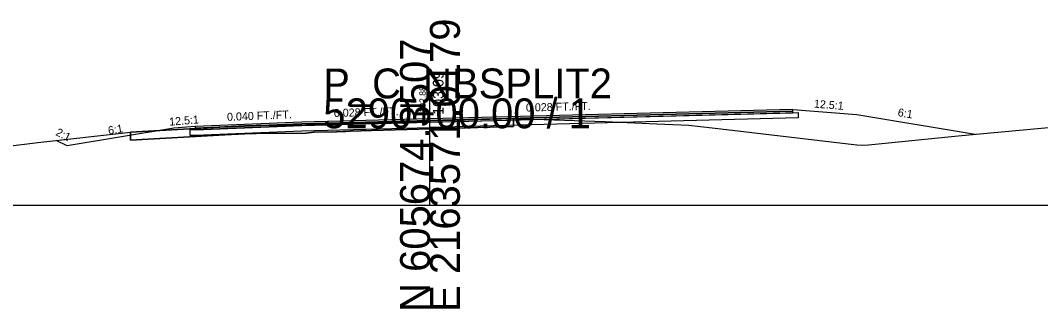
# Model space of a CAD drawing. Extents: x -26 to 1303, y -10 to 12038.
# Drawn here: x 111.6 to 207.2, y 5490.3 to 5517.3 of the extents above; entities that cross this region are included whole.
import ezdxf

# ---------------------------------------------------------------- set-up
doc = ezdxf.new("R2010")
doc.units = 0
for name, color, linetype in [('RD_GPK_XS_Cell', 7, 'Continuous'), ('RD_XS_Base', 7, 'Continuous'), ('RD_XS_ExGround', 7, 'Continuous'), ('RD_XS_ExPaveRet', 7, 'Continuous'), ('RD_XS_Greenside', 7, 'Continuous'), ('RD_XS_Pave', 7, 'Continuous'), ('RD_XS_PaveOvlay_CP', 7, 'Continuous'), ('RD_XS_TieSlope', 7, 'Continuous'), ('RD_XS_TX_Elev_EX', 7, 'Continuous'), ('RD_XS_TX_Elev_PR', 7, 'Continuous'), ('RD_XS_TX_ShdSlope', 7, 'Continuous'), ('RD_XS_TX_Slope', 7, 'Continuous')]:
    doc.layers.add(name, color=color, linetype=linetype)

msp = doc.modelspace()

# ---------------------------------------------------------------- linework, layer by layer
at = {"layer": 'RD_GPK_XS_Cell'}
for p, q in [((150, 5500), (150, 5510)), ((0, 5500), (150, 5500)), ((150, 5500), (300, 5500))]:
    msp.add_line(p, q, dxfattribs=at)
at = {"layer": 'RD_XS_Base'}
for p, q in [((150, 5507.772), (184.5, 5508.669)), ((174, 5508.396), (174, 5508.396)), ((174, 5508.396), (174, 5508.396)), ((184, 5508.656), (184, 5508.656)), ((184.5, 5508.669), (184.5, 5508.169)), ((184.5, 5508.636), (184.5, 5508.636)), ((138, 5507.46), (128, 5507.06)), ((150, 5507.772), (138, 5507.46)), ((138, 5507.46), (138, 5507.46)), ((184.5, 5508.169), (150, 5507.272)), ((150, 5507.272), (150, 5507.931)), ((150, 5507.931), (150, 5507.931)), ((150, 5507.931), (150, 5507.931)), ((150, 5507.931), (150, 5507.772)), ((150, 5507.772), (150, 5507.772)), ((150, 5507.272), (150, 5507.772)), ((150, 5507.772), (150, 5507.772)), ((150, 5507.772), (150, 5507.772)), ((174, 5507.896), (174, 5507.896)), ((174, 5507.896), (174, 5507.896)), ((128, 5507.06), (127.5, 5507.04)), ((127.5, 5507.04), (127.5, 5507.04)), ((127.5, 5507.04), (127.5, 5506.54)), ((127.5, 5506.54), (128, 5506.56)), ((128, 5507.06), (128, 5507.06)), ((128, 5506.56), (138, 5506.96)), ((128, 5506.56), (128, 5506.56)), ((138, 5506.96), (150, 5507.272)), ((138, 5506.96), (138, 5506.96)), ((150, 5507.272), (150, 5507.272))]:
    msp.add_line(p, q, dxfattribs=at)
at = {"layer": 'RD_XS_ExGround'}
msp.add_lwpolyline([(110.228, 5505.5), (113.26, 5505.871), (121.947, 5506.848), (130.783, 5507.333), (132.65, 5507.43), (133.697, 5507.462), (138.362, 5507.503), (139.162, 5507.596), (141.245, 5507.62), (141.848, 5507.644), (142.105, 5507.664), (142.506, 5507.669), (144.524, 5507.728), (157.841, 5508.109), (166.427, 5507.826), (171.259, 5507.611), (174.249, 5507.497), (176.44, 5507.25), (190.003, 5505.655), (190.532, 5505.607), (191.108, 5505.662), (199.491, 5506.499), (209.323, 5507.413)], dxfattribs=at)
at = {"layer": 'RD_XS_ExPaveRet'}
for points in [[(157.841, 5508.109), (157.841, 5508.109), (157.841, 5508.109), (157.841, 5507.359), (157.841, 5507.359), (144.524, 5506.978), (144.524, 5506.978), (142.506, 5506.919), (142.105, 5506.914), (142.105, 5506.914), (142.105, 5506.914), (141.848, 5506.894), (141.848, 5506.894), (141.245, 5506.87), (141.245, 5506.87), (141.245, 5506.87), (139.162, 5506.846), (138.362, 5506.753), (138.362, 5506.753), (133.697, 5506.712), (132.65, 5506.68), (132.65, 5506.68), (132.65, 5506.68), (130.783, 5506.583), (130.783, 5506.583), (121.948, 5506.098), (121.948, 5506.848), (121.948, 5506.848), (130.783, 5507.333), (130.783, 5507.333), (132.65, 5507.43), (132.65, 5507.43), (132.65, 5507.43), (133.697, 5507.462), (138.362, 5507.503), (138.362, 5507.503), (139.162, 5507.596), (141.245, 5507.62), (141.245, 5507.62), (141.245, 5507.62), (141.848, 5507.644), (141.848, 5507.644), (142.105, 5507.664), (142.105, 5507.664), (142.105, 5507.664), (142.506, 5507.669), (144.524, 5507.728), (144.524, 5507.728), (157.841, 5508.109)], [(144.524, 5507.728), (142.506, 5507.669), (142.105, 5507.664), (141.848, 5507.644), (141.245, 5507.62), (139.162, 5507.596), (138.362, 5507.503), (133.697, 5507.462), (132.65, 5507.43), (130.783, 5507.333), (121.948, 5506.848), (121.948, 5506.098), (130.783, 5506.583), (132.65, 5506.68), (133.697, 5506.712), (138.362, 5506.753), (139.162, 5506.846), (141.245, 5506.87), (141.848, 5506.894), (142.105, 5506.914), (142.506, 5506.919), (144.524, 5506.978), (157.841, 5507.359), (157.841, 5508.109), (144.524, 5507.728)]]:
    msp.add_lwpolyline(points, dxfattribs=at)
at = {"layer": 'RD_XS_Greenside'}
for p, q in [((190, 5508.494), (201.081, 5506.647)), ((126, 5507.218), (116, 5505.551)), ((116, 5505.551), (114.974, 5506.064))]:
    msp.add_line(p, q, dxfattribs=at)
at = {"layer": 'RD_XS_Pave'}
for p, q in [((184, 5508.974), (150, 5508.09)), ((184, 5508.815), (150, 5507.931)), ((150, 5507.931), (184, 5508.815)), ((150, 5507.772), (184, 5508.656)), ((174, 5508.714), (174, 5508.714)), ((174, 5508.714), (174, 5508.714)), ((174, 5508.555), (174, 5508.555)), ((174, 5508.555), (174, 5508.555)), ((174, 5508.555), (174, 5508.555)), ((174, 5508.555), (174, 5508.555)), ((174, 5508.396), (174, 5508.396)), ((174, 5508.396), (174, 5508.396)), ((184, 5508.815), (184, 5508.974)), ((184, 5508.974), (184, 5508.974)), ((184, 5508.656), (184, 5508.815)), ((184, 5508.815), (184, 5508.815)), ((138, 5507.778), (128, 5507.378)), ((128, 5507.219), (138, 5507.619)), ((138, 5507.619), (128, 5507.219)), ((128, 5507.06), (138, 5507.46)), ((128, 5507.378), (128, 5507.378)), ((128, 5507.378), (128, 5507.219)), ((150, 5508.09), (138, 5507.778)), ((138, 5507.619), (150, 5507.931)), ((150, 5507.931), (138, 5507.619)), ((138, 5507.778), (138, 5507.778)), ((138, 5507.46), (150, 5507.772)), ((138, 5507.619), (138, 5507.619)), ((138, 5507.619), (138, 5507.619)), ((138, 5507.46), (138, 5507.46)), ((150, 5508.09), (150, 5508.09)), ((150, 5507.931), (150, 5507.931)), ((150, 5507.931), (150, 5507.931)), ((150, 5507.931), (150, 5507.772)), ((150, 5507.931), (150, 5507.931)), ((150, 5507.772), (150, 5507.931)), ((150, 5507.931), (150, 5507.931)), ((150, 5507.931), (150, 5507.931)), ((150, 5507.772), (150, 5507.772)), ((150, 5507.772), (150, 5507.772)), ((128, 5507.219), (128, 5507.219)), ((128, 5507.219), (128, 5507.06))]:
    msp.add_line(p, q, dxfattribs=at)
at = {"layer": 'RD_XS_PaveOvlay_CP'}
for p, q in [((184, 5508.974), (150, 5508.09)), ((174, 5508.714), (174, 5508.714)), ((174, 5508.714), (174, 5508.714)), ((138, 5507.778), (128, 5507.378)), ((150, 5508.09), (138, 5507.778)), ((138, 5507.778), (138, 5507.778)), ((150, 5508.09), (150, 5508.09))]:
    msp.add_line(p, q, dxfattribs=at)
at = {"layer": 'RD_XS_TieSlope'}
for p, q in [((184, 5508.974), (190, 5508.494)), ((128, 5507.378), (126, 5507.218))]:
    msp.add_line(p, q, dxfattribs=at)

# ---------------------------------------------------------------- texts
at = {"layer": 'RD_GPK_XS_Cell'}
for s, p in [('E 2163571.0179', (152.8, 5490)), ('N 605674.3507', (150, 5490))]:
    msp.add_text(s, height=2.8, rotation=90, dxfattribs=at).set_placement(p)
for s, p in [('P_C_NBSPLIT2', (140, 5510)), ('5290+00.00 / 1', (140, 5507.2))]:
    msp.add_text(s, height=2.8, dxfattribs=at).set_placement(p)
at = {"layer": 'RD_XS_TX_Elev_EX'}
msp.add_text('102.88', height=0.6, rotation=90, dxfattribs=at).set_placement((149.606, 5508.682))
at = {"layer": 'RD_XS_TX_Elev_PR'}
msp.add_text('103.09', height=1, rotation=90, dxfattribs=at).set_placement((151.271, 5508.464))
at = {"layer": 'RD_XS_TX_ShdSlope'}
for rotation, p in [(355.42608, (185.961, 5509.141)), (4.57392, (125.587, 5507.438))]:
    msp.add_text('12.5:1', height=0.75, rotation=rotation, dxfattribs=at).set_placement(p)
at = {"layer": 'RD_XS_TX_Slope'}
for s, rotation, p in [('0.028 FT./FT.', 1.60386, (158.999, 5508.76)), ('0.040 FT./FT.', 2.29061, (130.995, 5507.892)), ('0.028 FT./FT.', 1.60386, (140.999, 5508.256)), ('6:1', 350.53768, (193.8, 5508.346)), ('6:1', 9.46418, (119.893, 5506.612)), ('2:1', 333.43495, (114.855, 5506.58))]:
    msp.add_text(s, height=0.75, rotation=rotation, dxfattribs=at).set_placement(p)

doc.saveas('drawing.dxf')
